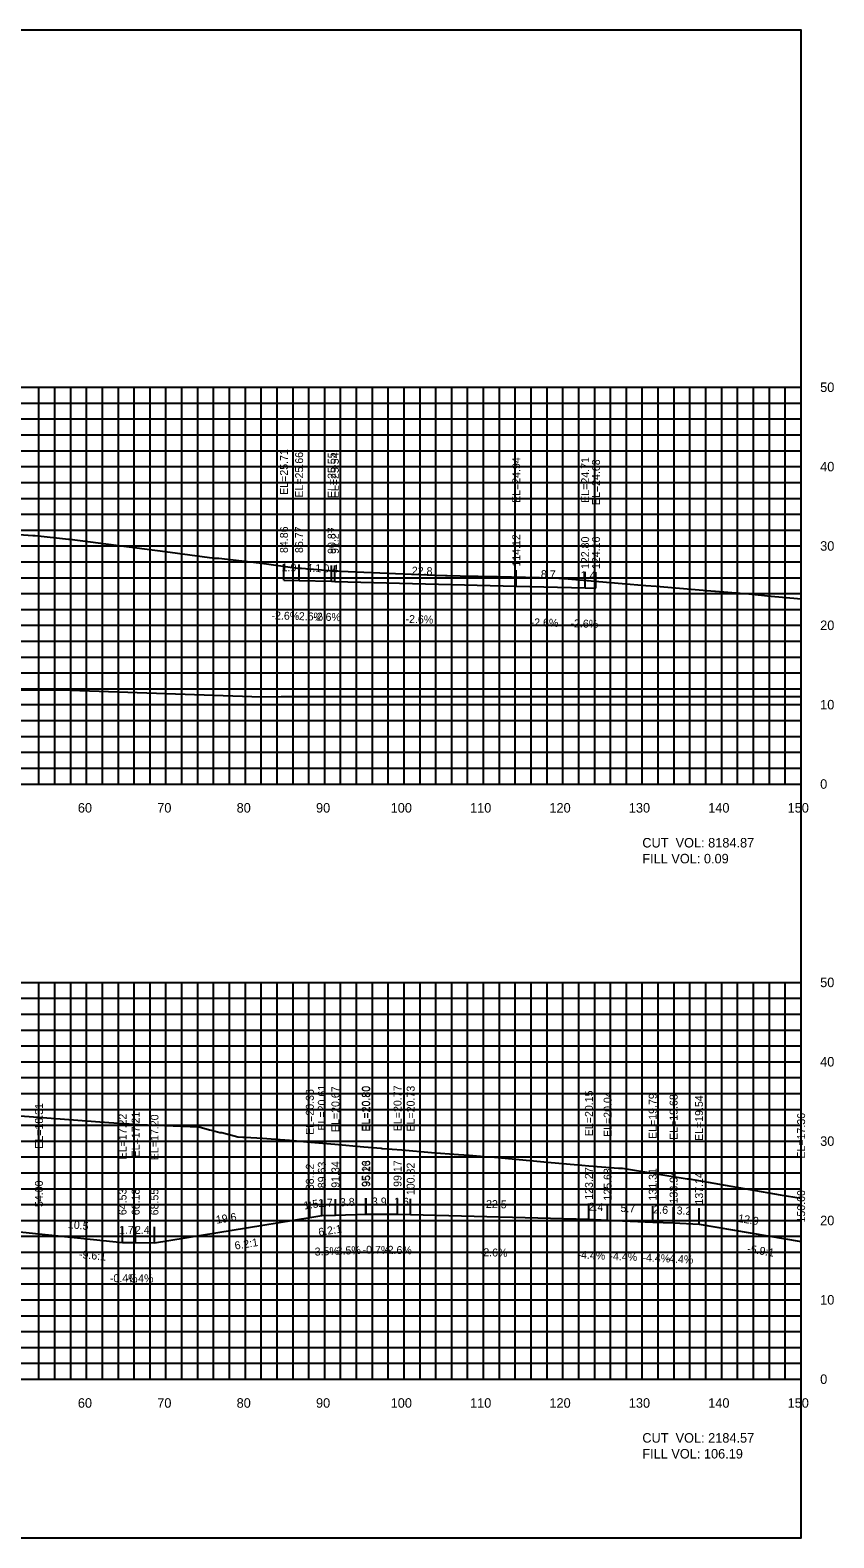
# Model space of a CAD drawing. Extents: x 1800880 to 1818864, y 245271 to 250560.
# Drawn here: x 1810265.7 to 1810366.9, y 250355.3 to 250545.3 of the extents above; entities that cross this region are included whole.
import ezdxf

# ---------------------------------------------------------------- set-up
doc = ezdxf.new("R2010")
doc.units = 0
for name, color, linetype in [('33', 7, 'Continuous'), ('ANNO-TXT', 7, 'Continuous'), ('CL-CNST', 7, 'Continuous'), ('DESIGN - DRAINAGE - Bridges', 7, 'Continuous'), ('DRAINAGETXT', 7, 'Continuous'), ('Level 37', 7, 'Continuous'), ('Level 46', 7, 'Continuous'), ('Level 62', 7, 'Continuous'), ('SHT-BDR', 7, 'Continuous')]:
    doc.layers.add(name, color=color, linetype=linetype)

msp = doc.modelspace()

# ---------------------------------------------------------------- linework, layer by layer
at = {"layer": 'CL-CNST'}
for points in [[(1810260.11, 250482.06), (1810266.05, 250481.64), (1810266.36, 250481.64), (1810270.55, 250481.17), (1810270.73, 250481.17), (1810282.73, 250479.62), (1810288.94, 250478.79), (1810289.22, 250478.79), (1810289.47, 250478.78), (1810294.55, 250478.19), (1810299.4, 250477.54), (1810299.75, 250477.54), (1810299.9, 250477.54), (1810303.41, 250477.23), (1810303.77, 250477.19), (1810316.74, 250476.62), (1810318.02, 250476.6), (1810318.23, 250476.6), (1810319.88, 250476.57), (1810322.16, 250476.53), (1810324.57, 250476.49), (1810326.34, 250476.45), (1810331.63, 250476.32), (1810332.99, 250476.2), (1810333.93, 250476.12), (1810334.89, 250476.04), (1810340.28, 250475.58), (1810343.26, 250475.35), (1810344.56, 250475.24), (1810347, 250475.06), (1810349.49, 250474.84), (1810351.96, 250474.63), (1810352.04, 250474.63), (1810353.59, 250474.5), (1810355.14, 250474.36), (1810356.23, 250474.27), (1810358.22, 250474.08), (1810358.57, 250474.05), (1810362.82, 250473.65)], [(1810264.46, 250408.51), (1810275.62, 250407.66), (1810280.13, 250407.37), (1810280.48, 250407.38), (1810286.91, 250407.1), (1810286.98, 250407.1), (1810288.29, 250406.76), (1810288.73, 250406.65), (1810289.61, 250406.42), (1810289.87, 250406.41), (1810291.86, 250405.84), (1810292.5, 250405.81), (1810292.79, 250405.8), (1810294.96, 250405.68), (1810296.05, 250405.62), (1810298.36, 250405.42), (1810300.56, 250405.23), (1810304.08, 250404.92), (1810307.73, 250404.6), (1810309.94, 250404.41), (1810310.04, 250404.4), (1810310.11, 250404.39), (1810312.53, 250404.2), (1810316.28, 250403.9), (1810319.68, 250403.62), (1810321.01, 250403.53), (1810323.35, 250403.35), (1810323.78, 250403.32), (1810324.2, 250403.29), (1810330.89, 250402.68), (1810333.75, 250402.41), (1810335.2, 250402.28), (1810336.08, 250402.2), (1810339.84, 250401.89), (1810340.2, 250401.89), (1810340.31, 250401.89), (1810348.46, 250400.56), (1810348.72, 250400.55), (1810360.2, 250398.56), (1810362.82, 250398.14)]]:
    msp.add_lwpolyline(points, dxfattribs=at)
at = {"layer": 'DESIGN - DRAINAGE - Bridges'}
for p, q in [((1810362.82, 250450.32), (1810362.82, 250500.32)), ((1810362.88, 250500.32), (1810362.82, 250500.32)), ((1810362.88, 250490.32), (1810362.82, 250490.32)), ((1810362.88, 250480.32), (1810362.82, 250480.32)), ((1810362.88, 250470.32), (1810362.82, 250470.32)), ((1810362.88, 250460.32), (1810362.82, 250460.32)), ((1810062.82, 250450.32), (1810362.82, 250450.32)), ((1810272.82, 250450.26), (1810272.82, 250450.32)), ((1810282.82, 250450.26), (1810282.82, 250450.32)), ((1810292.82, 250450.26), (1810292.82, 250450.32)), ((1810302.82, 250450.26), (1810302.82, 250450.32)), ((1810312.82, 250450.26), (1810312.82, 250450.32)), ((1810322.82, 250450.26), (1810322.82, 250450.32)), ((1810332.82, 250450.26), (1810332.82, 250450.32)), ((1810342.82, 250450.26), (1810342.82, 250450.32)), ((1810352.82, 250450.26), (1810352.82, 250450.32)), ((1810362.82, 250450.26), (1810362.82, 250450.32)), ((1810362.88, 250450.32), (1810362.82, 250450.32)), ((1810362.82, 250375.32), (1810362.82, 250425.32)), ((1810362.88, 250425.32), (1810362.82, 250425.32)), ((1810362.88, 250415.32), (1810362.82, 250415.32)), ((1810362.88, 250405.32), (1810362.82, 250405.32)), ((1810362.88, 250395.32), (1810362.82, 250395.32)), ((1810362.88, 250385.32), (1810362.82, 250385.32)), ((1810062.82, 250375.32), (1810362.82, 250375.32)), ((1810272.82, 250375.26), (1810272.82, 250375.32)), ((1810282.82, 250375.26), (1810282.82, 250375.32)), ((1810292.82, 250375.26), (1810292.82, 250375.32)), ((1810302.82, 250375.26), (1810302.82, 250375.32)), ((1810312.82, 250375.26), (1810312.82, 250375.32)), ((1810322.82, 250375.26), (1810322.82, 250375.32)), ((1810332.82, 250375.26), (1810332.82, 250375.32)), ((1810342.82, 250375.26), (1810342.82, 250375.32)), ((1810352.82, 250375.26), (1810352.82, 250375.32)), ((1810362.82, 250375.26), (1810362.82, 250375.32)), ((1810362.88, 250375.32), (1810362.82, 250375.32))]:
    msp.add_line(p, q, dxfattribs=at)
at = {"layer": 'Level 37'}
for p, q in [((1810297.68, 250476.03), (1810297.68, 250478.03)), ((1810299.59, 250475.98), (1810299.59, 250477.98)), ((1810303.69, 250475.87), (1810303.69, 250477.87)), ((1810304.09, 250475.86), (1810304.09, 250477.86)), ((1810326.94, 250475.26), (1810326.94, 250477.26)), ((1810335.62, 250475.04), (1810335.62, 250477.04)), ((1810336.98, 250475), (1810336.98, 250477)), ((1810300.94, 250395.68), (1810300.94, 250397.68)), ((1810302.45, 250395.93), (1810302.45, 250397.93)), ((1810304.16, 250395.99), (1810304.16, 250397.99)), ((1810307.98, 250396.12), (1810307.98, 250398.12)), ((1810308.05, 250396.13), (1810308.05, 250398.13)), ((1810311.99, 250396.1), (1810311.99, 250398.1)), ((1810313.64, 250396.05), (1810313.64, 250398.05)), ((1810336.09, 250395.47), (1810336.09, 250397.47)), ((1810338.45, 250395.37), (1810338.45, 250397.37)), ((1810266.82, 250393.64), (1810266.82, 250395.64)), ((1810344.13, 250395.12), (1810344.13, 250397.12)), ((1810346.76, 250395), (1810346.76, 250397)), ((1810349.96, 250394.86), (1810349.96, 250396.86)), ((1810277.35, 250392.54), (1810277.35, 250394.54)), ((1810279, 250392.53), (1810279, 250394.53)), ((1810281.37, 250392.52), (1810281.37, 250394.52)), ((1810362.82, 250392.68), (1810362.82, 250394.68))]:
    msp.add_line(p, q, dxfattribs=at)
msp.add_lwpolyline([(1810062.82, 250355.32), (1810362.82, 250355.32), (1810362.82, 250545.32), (1810062.82, 250545.32)], close=True, dxfattribs=at)
at = {"layer": 'Level 46'}
for p, q in [((1810062.82, 250500.32), (1810362.82, 250500.32)), ((1810266.82, 250450.32), (1810266.82, 250500.32)), ((1810268.82, 250450.32), (1810268.82, 250500.32)), ((1810270.82, 250450.32), (1810270.82, 250500.32)), ((1810272.82, 250450.32), (1810272.82, 250500.32)), ((1810274.82, 250450.32), (1810274.82, 250500.32)), ((1810276.82, 250450.32), (1810276.82, 250500.32)), ((1810278.82, 250450.32), (1810278.82, 250500.32)), ((1810280.82, 250450.32), (1810280.82, 250500.32)), ((1810282.82, 250450.32), (1810282.82, 250500.32)), ((1810284.82, 250450.32), (1810284.82, 250500.32)), ((1810286.82, 250450.32), (1810286.82, 250500.32)), ((1810288.82, 250450.32), (1810288.82, 250500.32)), ((1810290.82, 250450.32), (1810290.82, 250500.32)), ((1810292.82, 250450.32), (1810292.82, 250500.32)), ((1810294.82, 250450.32), (1810294.82, 250500.32)), ((1810296.82, 250450.32), (1810296.82, 250500.32)), ((1810298.82, 250450.32), (1810298.82, 250500.32)), ((1810300.82, 250450.32), (1810300.82, 250500.32)), ((1810302.82, 250450.32), (1810302.82, 250500.32)), ((1810304.82, 250450.32), (1810304.82, 250500.32)), ((1810306.82, 250450.32), (1810306.82, 250500.32)), ((1810308.82, 250450.32), (1810308.82, 250500.32)), ((1810310.82, 250450.32), (1810310.82, 250500.32)), ((1810312.82, 250450.32), (1810312.82, 250500.32)), ((1810314.82, 250450.32), (1810314.82, 250500.32)), ((1810316.82, 250450.32), (1810316.82, 250500.32)), ((1810318.82, 250450.32), (1810318.82, 250500.32)), ((1810320.82, 250450.32), (1810320.82, 250500.32)), ((1810322.82, 250450.32), (1810322.82, 250500.32)), ((1810324.82, 250450.32), (1810324.82, 250500.32)), ((1810326.82, 250450.32), (1810326.82, 250500.32)), ((1810328.82, 250450.32), (1810328.82, 250500.32)), ((1810330.82, 250450.32), (1810330.82, 250500.32)), ((1810332.82, 250450.32), (1810332.82, 250500.32)), ((1810334.82, 250450.32), (1810334.82, 250500.32)), ((1810336.82, 250450.32), (1810336.82, 250500.32)), ((1810338.82, 250450.32), (1810338.82, 250500.32)), ((1810340.82, 250450.32), (1810340.82, 250500.32)), ((1810342.82, 250450.32), (1810342.82, 250500.32)), ((1810344.82, 250450.32), (1810344.82, 250500.32)), ((1810346.82, 250450.32), (1810346.82, 250500.32)), ((1810348.82, 250450.32), (1810348.82, 250500.32)), ((1810350.82, 250450.32), (1810350.82, 250500.32)), ((1810352.82, 250450.32), (1810352.82, 250500.32)), ((1810354.82, 250450.32), (1810354.82, 250500.32)), ((1810356.82, 250450.32), (1810356.82, 250500.32)), ((1810358.82, 250450.32), (1810358.82, 250500.32)), ((1810360.82, 250450.32), (1810360.82, 250500.32)), ((1810362.82, 250450.32), (1810362.82, 250500.32)), ((1810062.82, 250498.32), (1810362.82, 250498.32)), ((1810062.82, 250496.32), (1810362.82, 250496.32)), ((1810062.82, 250494.32), (1810362.82, 250494.32)), ((1810062.82, 250492.32), (1810362.82, 250492.32)), ((1810062.82, 250490.32), (1810362.82, 250490.32)), ((1810062.82, 250488.32), (1810362.82, 250488.32)), ((1810062.82, 250486.32), (1810362.82, 250486.32)), ((1810062.82, 250484.32), (1810362.82, 250484.32)), ((1810062.82, 250482.32), (1810362.82, 250482.32)), ((1810062.82, 250480.32), (1810362.82, 250480.32)), ((1810062.82, 250478.32), (1810362.82, 250478.32)), ((1810062.82, 250476.32), (1810362.82, 250476.32)), ((1810062.82, 250474.32), (1810362.82, 250474.32)), ((1810062.82, 250472.32), (1810362.82, 250472.32)), ((1810062.82, 250470.32), (1810362.82, 250470.32)), ((1810062.82, 250468.32), (1810362.82, 250468.32)), ((1810062.82, 250466.32), (1810362.82, 250466.32)), ((1810062.82, 250464.32), (1810362.82, 250464.32)), ((1810062.82, 250462.32), (1810362.82, 250462.32)), ((1810062.82, 250460.32), (1810362.82, 250460.32)), ((1810062.82, 250458.32), (1810362.82, 250458.32)), ((1810062.82, 250456.32), (1810362.82, 250456.32)), ((1810062.82, 250454.32), (1810362.82, 250454.32)), ((1810062.82, 250452.32), (1810362.82, 250452.32)), ((1810062.82, 250450.32), (1810362.82, 250450.32)), ((1810062.82, 250425.32), (1810362.82, 250425.32)), ((1810266.82, 250375.32), (1810266.82, 250425.32)), ((1810268.82, 250375.32), (1810268.82, 250425.32)), ((1810270.82, 250375.32), (1810270.82, 250425.32)), ((1810272.82, 250375.32), (1810272.82, 250425.32)), ((1810274.82, 250375.32), (1810274.82, 250425.32)), ((1810276.82, 250375.32), (1810276.82, 250425.32)), ((1810278.82, 250375.32), (1810278.82, 250425.32)), ((1810280.82, 250375.32), (1810280.82, 250425.32)), ((1810282.82, 250375.32), (1810282.82, 250425.32)), ((1810284.82, 250375.32), (1810284.82, 250425.32)), ((1810286.82, 250375.32), (1810286.82, 250425.32)), ((1810288.82, 250375.32), (1810288.82, 250425.32)), ((1810290.82, 250375.32), (1810290.82, 250425.32)), ((1810292.82, 250375.32), (1810292.82, 250425.32)), ((1810294.82, 250375.32), (1810294.82, 250425.32)), ((1810296.82, 250375.32), (1810296.82, 250425.32)), ((1810298.82, 250375.32), (1810298.82, 250425.32)), ((1810300.82, 250375.32), (1810300.82, 250425.32)), ((1810302.82, 250375.32), (1810302.82, 250425.32)), ((1810304.82, 250375.32), (1810304.82, 250425.32)), ((1810306.82, 250375.32), (1810306.82, 250425.32)), ((1810308.82, 250375.32), (1810308.82, 250425.32)), ((1810310.82, 250375.32), (1810310.82, 250425.32)), ((1810312.82, 250375.32), (1810312.82, 250425.32)), ((1810314.82, 250375.32), (1810314.82, 250425.32)), ((1810316.82, 250375.32), (1810316.82, 250425.32)), ((1810318.82, 250375.32), (1810318.82, 250425.32)), ((1810320.82, 250375.32), (1810320.82, 250425.32)), ((1810322.82, 250375.32), (1810322.82, 250425.32)), ((1810324.82, 250375.32), (1810324.82, 250425.32)), ((1810326.82, 250375.32), (1810326.82, 250425.32)), ((1810328.82, 250375.32), (1810328.82, 250425.32)), ((1810330.82, 250375.32), (1810330.82, 250425.32)), ((1810332.82, 250375.32), (1810332.82, 250425.32)), ((1810334.82, 250375.32), (1810334.82, 250425.32)), ((1810336.82, 250375.32), (1810336.82, 250425.32)), ((1810338.82, 250375.32), (1810338.82, 250425.32)), ((1810340.82, 250375.32), (1810340.82, 250425.32)), ((1810342.82, 250375.32), (1810342.82, 250425.32)), ((1810344.82, 250375.32), (1810344.82, 250425.32)), ((1810346.82, 250375.32), (1810346.82, 250425.32)), ((1810348.82, 250375.32), (1810348.82, 250425.32)), ((1810350.82, 250375.32), (1810350.82, 250425.32)), ((1810352.82, 250375.32), (1810352.82, 250425.32)), ((1810354.82, 250375.32), (1810354.82, 250425.32)), ((1810356.82, 250375.32), (1810356.82, 250425.32)), ((1810358.82, 250375.32), (1810358.82, 250425.32)), ((1810360.82, 250375.32), (1810360.82, 250425.32)), ((1810362.82, 250375.32), (1810362.82, 250425.32)), ((1810062.82, 250423.32), (1810362.82, 250423.32)), ((1810062.82, 250421.32), (1810362.82, 250421.32)), ((1810062.82, 250419.32), (1810362.82, 250419.32)), ((1810062.82, 250417.32), (1810362.82, 250417.32)), ((1810062.82, 250415.32), (1810362.82, 250415.32)), ((1810062.82, 250413.32), (1810362.82, 250413.32)), ((1810062.82, 250411.32), (1810362.82, 250411.32)), ((1810062.82, 250409.32), (1810362.82, 250409.32)), ((1810062.82, 250407.32), (1810362.82, 250407.32)), ((1810062.82, 250405.32), (1810362.82, 250405.32)), ((1810062.82, 250403.32), (1810362.82, 250403.32)), ((1810062.82, 250401.32), (1810362.82, 250401.32)), ((1810062.82, 250399.32), (1810362.82, 250399.32)), ((1810062.82, 250397.32), (1810362.82, 250397.32)), ((1810062.82, 250395.32), (1810362.82, 250395.32)), ((1810062.82, 250393.32), (1810362.82, 250393.32)), ((1810062.82, 250391.32), (1810362.82, 250391.32)), ((1810062.82, 250389.32), (1810362.82, 250389.32)), ((1810062.82, 250387.32), (1810362.82, 250387.32)), ((1810062.82, 250385.32), (1810362.82, 250385.32)), ((1810062.82, 250383.32), (1810362.82, 250383.32)), ((1810062.82, 250381.32), (1810362.82, 250381.32)), ((1810062.82, 250379.32), (1810362.82, 250379.32)), ((1810062.82, 250377.32), (1810362.82, 250377.32)), ((1810062.82, 250375.32), (1810362.82, 250375.32))]:
    msp.add_line(p, q, dxfattribs=at)
at = {"layer": 'Level 62'}
for points in [[(1810297.68, 250476.03), (1810299.59, 250475.98), (1810303.69, 250475.87), (1810304.09, 250475.86), (1810326.94, 250475.26), (1810335.62, 250475.04), (1810336.98, 250475)], [(1810062.82, 250462.47), (1810075.3, 250462.39), (1810077.68, 250462.39), (1810103.06, 250462.32), (1810107.83, 250462.34), (1810130.81, 250462.36), (1810137.65, 250462.4), (1810158.57, 250462.04), (1810167.21, 250462.09), (1810186.32, 250462.29), (1810203.94, 250462.18), (1810214.08, 250462.24), (1810231.53, 250462.53), (1810241.83, 250462.6), (1810259.07, 250462.13), (1810269.59, 250462.19), (1810294.84, 250461.32), (1810297.34, 250461.33), (1810323.18, 250461.33), (1810325.1, 250461.34), (1810351.05, 250461.34), (1810352.85, 250461.35), (1810362.82, 250461.35)], [(1810197.19, 250400.88), (1810199.38, 250400.65), (1810204.88, 250400.08), (1810223.4, 250398.15), (1810266.82, 250393.64), (1810277.35, 250392.54), (1810279, 250392.53), (1810281.37, 250392.52), (1810300.94, 250395.68), (1810302.45, 250395.93), (1810304.16, 250395.99), (1810307.98, 250396.12), (1810308.05, 250396.13), (1810311.99, 250396.1), (1810313.64, 250396.05), (1810336.09, 250395.47), (1810338.45, 250395.37), (1810344.13, 250395.12), (1810346.76, 250395), (1810349.96, 250394.86), (1810362.82, 250392.68)]]:
    msp.add_lwpolyline(points, dxfattribs=at)

# ---------------------------------------------------------------- texts
for s, p in [('60', (1810271.72, 250446.72)), ('70', (1810281.72, 250446.72)), ('80', (1810291.72, 250446.72)), ('90', (1810301.72, 250446.72)), ('100', (1810311.12, 250446.72)), ('110', (1810321.12, 250446.72)), ('120', (1810331.12, 250446.72)), ('130', (1810341.12, 250446.72)), ('140', (1810351.12, 250446.72)), ('150', (1810361.12, 250446.72)), ('60', (1810271.72, 250371.72)), ('70', (1810281.72, 250371.72)), ('80', (1810291.72, 250371.72)), ('90', (1810301.72, 250371.72)), ('100', (1810311.12, 250371.72)), ('110', (1810321.12, 250371.72)), ('120', (1810331.12, 250371.72)), ('130', (1810341.12, 250371.72)), ('140', (1810351.12, 250371.72)), ('150', (1810361.12, 250371.72))]:
    msp.add_text(s, height=1.2).set_placement(p)
at = {"layer": '33'}
for s, p in [('50', (1810365.22, 250499.72)), ('40', (1810365.22, 250489.72)), ('30', (1810365.22, 250479.72)), ('20', (1810365.22, 250469.72)), ('10', (1810365.22, 250459.72)), ('0', (1810365.22, 250449.72)), ('50', (1810365.22, 250424.72)), ('40', (1810365.22, 250414.72)), ('30', (1810365.22, 250404.72)), ('20', (1810365.22, 250394.72)), ('10', (1810365.22, 250384.72)), ('0', (1810365.22, 250374.72))]:
    msp.add_text(s, height=1.2, dxfattribs=at).set_placement(p)
at = {"layer": 'ANNO-TXT'}
for s, rotation, p in [('1.9', 358.4952, (1810297.38, 250477.14)), ('4.1', 358.4952, (1810300.51, 250477.06)), ('0.4', 358.4952, (1810302.64, 250477)), ('22.8', 358.4952, (1810313.77, 250476.71)), ('8.7', 358.4952, (1810330.03, 250476.28)), ('1.4', 358.4952, (1810335.05, 250476.15)), ('-2.6%', 358.4952, (1810296.1, 250471.07)), ('-2.6%', 358.4952, (1810299.1, 250470.99)), ('-2.6%', 358.4952, (1810301.35, 250470.93)), ('-2.6%', 358.4952, (1810312.98, 250470.63)), ('-2.6%', 358.4952, (1810328.74, 250470.21)), ('-2.6%', 358.4952, (1810333.76, 250470.08)), ('1.5', 9.176, (1810300.25, 250396.69)), ('1.7', 2.0271, (1810301.99, 250397.01)), ('3.8', 2.0146, (1810304.75, 250397.11)), ('3.9', 359.584, (1810308.75, 250397.22)), ('1.6', 358.5099, (1810311.54, 250397.21)), ('22.5', 358.5099, (1810323.12, 250396.91)), ('2.4', 357.4842, (1810336.04, 250396.57)), ('5.7', 357.4842, (1810340.05, 250396.4)), ('2.6', 357.4842, (1810344.19, 250396.22)), ('10.5', 354.0613, (1810270.43, 250394.37)), ('19.6', 9.176, (1810289.2, 250394.9)), ('3.2', 357.4842, (1810347.12, 250396.09)), ('12.9', 350.3949, (1810354.82, 250395.15)), ('1.7', 359.7457, (1810276.9, 250393.64)), ('2.4', 359.7457, (1810278.91, 250393.63)), ('3.5%', 2.0271, (1810301.57, 250390.89)), ('3.5%', 2.0146, (1810304.33, 250390.99)), ('-0.7%', 359.584, (1810307.58, 250391.13)), ('-2.6%', 358.5099, (1810310.28, 250391.14)), ('-2.6%', 358.5099, (1810322.33, 250390.83)), ('-4.4%', 357.4842, (1810334.64, 250390.53)), ('-4.4%', 357.4842, (1810338.66, 250390.35)), ('-4.4%', 357.4842, (1810342.82, 250390.17)), ('-4.4%', 357.4842, (1810345.73, 250390.04)), ('-0.4%', 359.7457, (1810275.75, 250387.55)), ('-0.4%', 359.7457, (1810277.75, 250387.54))]:
    msp.add_text(s, height=1, rotation=rotation, dxfattribs=at).set_placement(p)
at = {"layer": 'DRAINAGETXT'}
for s, p in [('CUT  VOL: 8184.87', (1810342.82, 250442.32)), ('FILL VOL: 0.09', (1810342.82, 250440.32)), ('CUT  VOL: 2184.57', (1810342.82, 250367.32)), ('FILL VOL: 106.19', (1810342.82, 250365.32))]:
    msp.add_text(s, height=1.2, dxfattribs=at).set_placement(p)
at = {"layer": 'Level 37'}
for s, rotation, p in [('6.2:1', 9.176, (1810302.1, 250393.34)), ('-9.6:1', 354.0613, (1810271.83, 250390.6)), ('6.2:1', 9.176, (1810291.55, 250391.64)), ('-5.9:1', 350.3949, (1810355.97, 250391.31))]:
    msp.add_text(s, height=1, rotation=rotation, dxfattribs=at).set_placement(p)
at = {"layer": 'SHT-BDR'}
for s, p in [('EL=25.71', (1810298.18, 250486.76)), ('EL=25.66', (1810300.09, 250486.41)), ('EL=25.55', (1810304.19, 250486.35)), ('EL=25.54', (1810304.59, 250486.34)), ('EL=24.94', (1810327.44, 250485.74)), ('EL=24.71', (1810336.12, 250485.76)), ('EL=24.68', (1810337.48, 250485.47)), ('84.86', (1810298.18, 250479.43)), ('86.77', (1810300.09, 250479.43)), ('90.87', (1810304.19, 250479.32)), ('91.27', (1810304.59, 250479.31)), ('114.12', (1810327.44, 250477.72)), ('122.80', (1810336.12, 250477.41)), ('124.16', (1810337.48, 250477.41)), ('EL=20.36', (1810301.44, 250406.11)), ('EL=20.61', (1810302.95, 250406.65)), ('EL=20.67', (1810304.66, 250406.46)), ('EL=20.80', (1810308.48, 250406.52)), ('EL=20.80', (1810308.55, 250406.52)), ('EL=20.77', (1810312.49, 250406.57)), ('EL=20.73', (1810314.14, 250406.53)), ('EL=20.15', (1810336.59, 250405.94)), ('EL=20.04', (1810338.95, 250405.84)), ('EL=19.79', (1810344.63, 250405.59)), ('EL=19.68', (1810347.26, 250405.47)), ('EL=19.54', (1810350.46, 250405.33)), ('EL=18.31', (1810267.32, 250404.36)), ('EL=17.22', (1810277.85, 250403.01)), ('EL=17.21', (1810279.5, 250403.26)), ('EL=17.20', (1810281.87, 250402.92)), ('EL=17.36', (1810363.32, 250403.11)), ('88.12', (1810301.44, 250399.13)), ('89.63', (1810302.95, 250399.38)), ('91.34', (1810304.66, 250399.44)), ('95.16', (1810308.48, 250399.53)), ('95.23', (1810308.55, 250399.57)), ('99.17', (1810312.49, 250399.55)), ('100.82', (1810314.14, 250398.51)), ('123.27', (1810336.59, 250397.93)), ('125.63', (1810338.95, 250397.82)), ('131.31', (1810344.63, 250397.83)), ('133.94', (1810347.26, 250397.46)), ('137.14', (1810350.46, 250397.32)), ('54.00', (1810267.32, 250397.01)), ('64.53', (1810277.85, 250395.99)), ('66.18', (1810279.5, 250395.98)), ('68.55', (1810281.87, 250395.97)), ('150.00', (1810363.32, 250395.06))]:
    msp.add_text(s, height=1, rotation=90, dxfattribs=at).set_placement(p)

doc.saveas('drawing.dxf')
